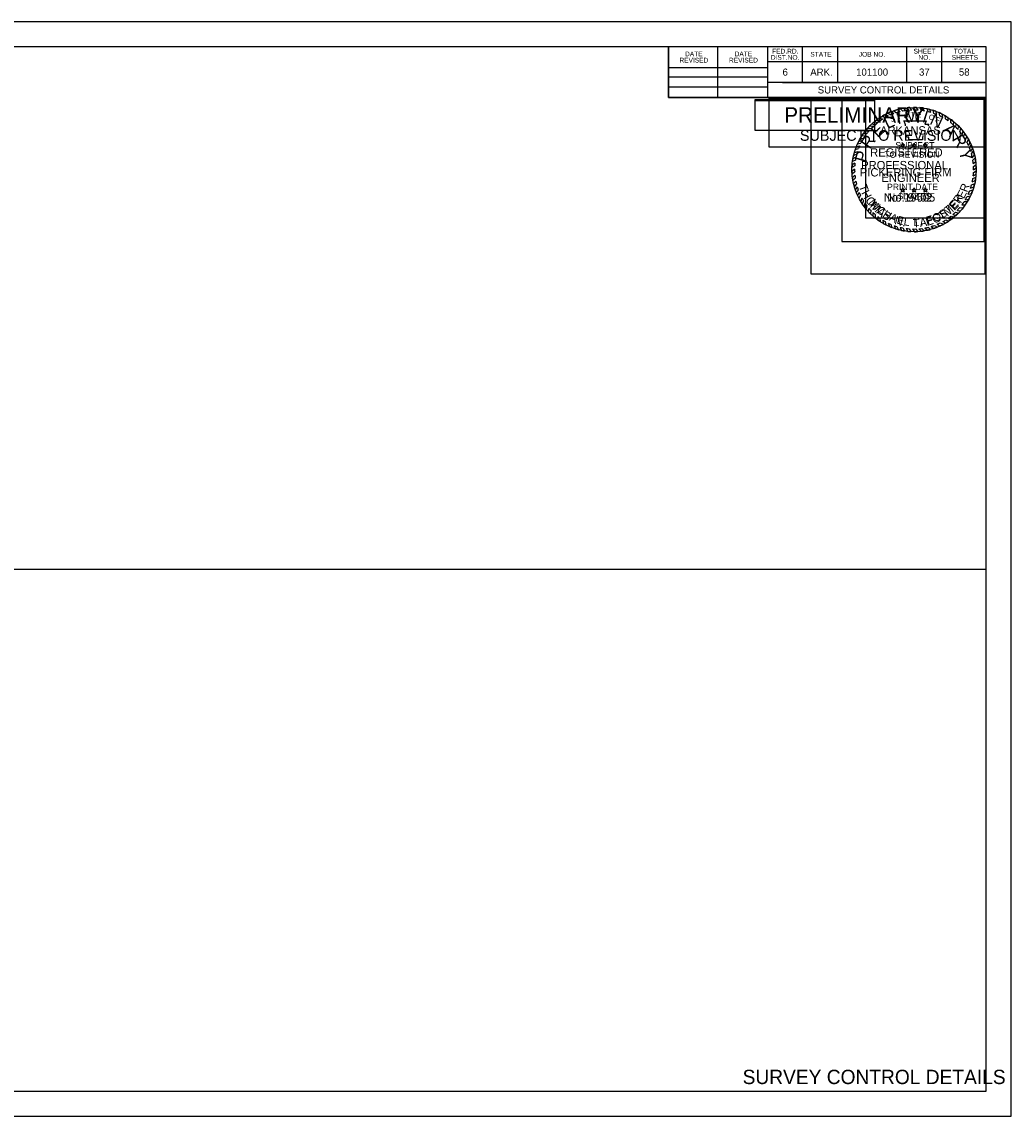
# Model space of a CAD drawing. Extents: x -0.24 to 1.42, y -0.07 to 0.92.
# Drawn here: x 0.588 to 1.417, y 0 to 0.917 of the extents above; entities that cross this region are included whole.
import ezdxf

# ---------------------------------------------------------------- set-up
doc = ezdxf.new("R2010")
doc.units = 0
for name, color, linetype in [('S_BRIDGE_ANNOT', 7, 'Continuous'), ('S_CROSS_DRAIN_ANNOT', 7, 'Continuous'), ('S_DRG_PT_SYM', 7, 'Continuous'), ('S_MSC_PT_SYM', 7, 'Continuous'), ('S_SECONDARY_CTL', 7, 'Continuous'), ('S_SIDE_DRAIN_ANNOT', 7, 'Continuous'), ('S_SURVEY_TEXT_ANNOT', 7, 'Continuous'), ('S_TELEPHONE_UTILITIES_ANNOT', 7, 'Continuous'), ('S_UNDERGROUND_CABLE', 7, 'Continuous'), ('S_UNDERGROUND_CABLE_ANNOT', 7, 'Continuous'), ('S_UTILITY_POLE', 7, 'Continuous'), ('S_UTL_PT_SYM', 7, 'Continuous')]:
    doc.layers.add(name, color=color, linetype=linetype)

msp = doc.modelspace()

# ---------------------------------------------------------------- linework, layer by layer
at = {"layer": 'S_BRIDGE_ANNOT'}
for p, q in [((1.3239, 0.84376), (1.32589, 0.84184)), ((1.32659, 0.8443), (1.32826, 0.84225)), ((1.32947, 0.84471), (1.33104, 0.84257)), ((1.33358, 0.84273), (1.33184, 0.84492)), ((1.33636, 0.84275), (1.33481, 0.84504)), ((1.33892, 0.84264), (1.33748, 0.84501)), ((1.34175, 0.84236), (1.34012, 0.84484)), ((1.34413, 0.84199), (1.34269, 0.84454)), ((1.34727, 0.84133), (1.3463, 0.8439)), ((1.34951, 0.84073), (1.34862, 0.84335)), ((1.30423, 0.83485), (1.30678, 0.8337)), ((1.30658, 0.83634), (1.30905, 0.83521)), ((1.30874, 0.8377), (1.31115, 0.83645)), ((1.31124, 0.8391), (1.31383, 0.83784)), ((1.31365, 0.84028), (1.31583, 0.83875)), ((1.31649, 0.84149), (1.31813, 0.83967)), ((1.31843, 0.8422), (1.32056, 0.84049)), ((1.32173, 0.84322), (1.32334, 0.84128)), ((1.35204, 0.83991), (1.35125, 0.84258)), ((1.35437, 0.83901), (1.35357, 0.84178)), ((1.35695, 0.83787), (1.35638, 0.84064)), ((1.35944, 0.83658), (1.35895, 0.83943)), ((1.36161, 0.83532), (1.36138, 0.83811)), ((1.36403, 0.83372), (1.36386, 0.8366)), ((1.36605, 0.83223), (1.36624, 0.83495)), ((1.2946, 0.82531), (1.29766, 0.82544)), ((1.29653, 0.82761), (1.29944, 0.8274)), ((1.29833, 0.82953), (1.30137, 0.8293)), ((1.3002, 0.83134), (1.30277, 0.83056)), ((1.30212, 0.83302), (1.30508, 0.83246)), ((1.32689, 0.8337), (1.34557, 0.8337)), ((1.32756, 0.83198), (1.32689, 0.8337)), ((1.32814, 0.83032), (1.32756, 0.83198)), ((1.32818, 0.82968), (1.32814, 0.83032)), ((1.34557, 0.8337), (1.34431, 0.83095)), ((1.34431, 0.83095), (1.34785, 0.83095)), ((1.34785, 0.83095), (1.34704, 0.82968)), ((1.36854, 0.83015), (1.36865, 0.83307)), ((1.37029, 0.82851), (1.37068, 0.8313)), ((1.37229, 0.82643), (1.37267, 0.82937)), ((1.37382, 0.82466), (1.37459, 0.82729)), ((1.37563, 0.82233), (1.37639, 0.82512)), ((1.28907, 0.81672), (1.29185, 0.81708)), ((1.29036, 0.81909), (1.29309, 0.8192)), ((1.29173, 0.82133), (1.29462, 0.82151)), ((1.29304, 0.82325), (1.29586, 0.82322)), ((1.32925, 0.82013), (1.32911, 0.82135)), ((1.33101, 0.82013), (1.32925, 0.82013)), ((1.33101, 0.81773), (1.33101, 0.82013)), ((1.34235, 0.81773), (1.33101, 0.81773)), ((1.34243, 0.81962), (1.34235, 0.81773)), ((1.34287, 0.82135), (1.34243, 0.81962)), ((1.37686, 0.82057), (1.37786, 0.82316)), ((1.37858, 0.81779), (1.3796, 0.82053)), ((1.3797, 0.81574), (1.38096, 0.81822)), ((1.28527, 0.80705), (1.28794, 0.80799)), ((1.28615, 0.80986), (1.28886, 0.81062)), ((1.28699, 0.81213), (1.28981, 0.81295)), ((1.28802, 0.81455), (1.29082, 0.81513)), ((1.32525, 0.81292), (1.32414, 0.81372)), ((1.32414, 0.81372), (1.32551, 0.81372)), ((1.32482, 0.81161), (1.32525, 0.81292)), ((1.32593, 0.81242), (1.32482, 0.81161)), ((1.32551, 0.81372), (1.32593, 0.81503)), ((1.32593, 0.81503), (1.32635, 0.81372)), ((1.32704, 0.81161), (1.32593, 0.81242)), ((1.32635, 0.81372), (1.32772, 0.81372)), ((1.32772, 0.81372), (1.32662, 0.81292)), ((1.32662, 0.81292), (1.32704, 0.81161)), ((1.33473, 0.81292), (1.33362, 0.81372)), ((1.33362, 0.81372), (1.33499, 0.81372)), ((1.33431, 0.81161), (1.33473, 0.81292)), ((1.33542, 0.81242), (1.33431, 0.81161)), ((1.33499, 0.81372), (1.33542, 0.81503)), ((1.33542, 0.81503), (1.33584, 0.81372)), ((1.33652, 0.81161), (1.33542, 0.81242)), ((1.33584, 0.81372), (1.33721, 0.81372)), ((1.33721, 0.81372), (1.3361, 0.81292)), ((1.3361, 0.81292), (1.33652, 0.81161)), ((1.34422, 0.81292), (1.34311, 0.81372)), ((1.34311, 0.81372), (1.34448, 0.81372)), ((1.34379, 0.81161), (1.34422, 0.81292)), ((1.3449, 0.81242), (1.34379, 0.81161)), ((1.34448, 0.81372), (1.3449, 0.81503)), ((1.3449, 0.81503), (1.34533, 0.81372)), ((1.34601, 0.81161), (1.3449, 0.81242)), ((1.34533, 0.81372), (1.3467, 0.81372)), ((1.3467, 0.81372), (1.34559, 0.81292)), ((1.34559, 0.81292), (1.34601, 0.81161)), ((1.38099, 0.81304), (1.38225, 0.81575)), ((1.38177, 0.81115), (1.38325, 0.81358)), ((1.38286, 0.80809), (1.38437, 0.81074)), ((1.38346, 0.80605), (1.3851, 0.80858)), ((1.28592, 0.7984), (1.28348, 0.79683)), ((1.28625, 0.80084), (1.28376, 0.79959)), ((1.28672, 0.8034), (1.28412, 0.80201)), ((1.28469, 0.80477), (1.28732, 0.80585)), ((1.38421, 0.80293), (1.38599, 0.80543)), ((1.38459, 0.80081), (1.38657, 0.80278)), ((1.38496, 0.79796), (1.38704, 0.79984)), ((1.28571, 0.79603), (1.28336, 0.79459)), ((1.28562, 0.79327), (1.28336, 0.7914)), ((1.28566, 0.791), (1.28347, 0.78918)), ((1.38493, 0.78764), (1.38735, 0.78907)), ((1.38514, 0.79563), (1.38732, 0.79726)), ((1.38515, 0.79047), (1.38749, 0.79202)), ((1.38521, 0.79273), (1.38748, 0.79453)), ((1.28584, 0.78823), (1.28377, 0.78624)), ((1.28613, 0.78583), (1.28416, 0.78375)), ((1.28657, 0.78327), (1.28468, 0.78122)), ((1.2871, 0.78093), (1.28535, 0.77861)), ((1.38354, 0.78015), (1.38617, 0.78128)), ((1.38414, 0.78268), (1.38668, 0.78377)), ((1.38465, 0.78547), (1.38712, 0.7867)), ((1.28779, 0.77843), (1.28614, 0.7761)), ((1.28857, 0.77607), (1.287, 0.77377)), ((1.2895, 0.77369), (1.28804, 0.77133)), ((1.29046, 0.77154), (1.28919, 0.76897)), ((1.32525, 0.77545), (1.32414, 0.77625)), ((1.32414, 0.77625), (1.32551, 0.77625)), ((1.32482, 0.77414), (1.32525, 0.77545)), ((1.32593, 0.77495), (1.32482, 0.77414)), ((1.32551, 0.77625), (1.32593, 0.77755)), ((1.32593, 0.77755), (1.32635, 0.77625)), ((1.32704, 0.77414), (1.32593, 0.77495)), ((1.32635, 0.77625), (1.32772, 0.77625)), ((1.32772, 0.77625), (1.32662, 0.77545)), ((1.32662, 0.77545), (1.32704, 0.77414)), ((1.33473, 0.77545), (1.33362, 0.77625)), ((1.33362, 0.77625), (1.33499, 0.77625)), ((1.33431, 0.77414), (1.33473, 0.77545)), ((1.33542, 0.77495), (1.33431, 0.77414)), ((1.33499, 0.77625), (1.33542, 0.77755)), ((1.33542, 0.77755), (1.33584, 0.77625)), ((1.33652, 0.77414), (1.33542, 0.77495)), ((1.33584, 0.77625), (1.33721, 0.77625)), ((1.33721, 0.77625), (1.3361, 0.77545)), ((1.3361, 0.77545), (1.33652, 0.77414)), ((1.34422, 0.77545), (1.34311, 0.77625)), ((1.34311, 0.77625), (1.34448, 0.77625)), ((1.34379, 0.77414), (1.34422, 0.77545)), ((1.3449, 0.77495), (1.34379, 0.77414)), ((1.34448, 0.77625), (1.3449, 0.77755)), ((1.3449, 0.77755), (1.34533, 0.77625)), ((1.34601, 0.77414), (1.3449, 0.77495)), ((1.34533, 0.77625), (1.3467, 0.77625)), ((1.3467, 0.77625), (1.34559, 0.77545)), ((1.34559, 0.77545), (1.34601, 0.77414)), ((1.37987, 0.77052), (1.38259, 0.7709)), ((1.38077, 0.7724), (1.38349, 0.77294)), ((1.38196, 0.77527), (1.38466, 0.776)), ((1.38272, 0.77739), (1.38546, 0.77851)), ((1.29177, 0.76898), (1.29071, 0.76625)), ((1.29309, 0.76673), (1.29206, 0.7641)), ((1.29422, 0.76499), (1.29361, 0.7619)), ((1.29579, 0.76281), (1.29522, 0.75984)), ((1.37377, 0.7612), (1.37635, 0.76076)), ((1.37549, 0.7634), (1.37831, 0.76342)), ((1.37739, 0.76616), (1.38005, 0.76613)), ((1.37835, 0.76773), (1.38115, 0.76804)), ((1.29749, 0.7607), (1.297, 0.75779)), ((1.29918, 0.75881), (1.29883, 0.75589)), ((1.30098, 0.75699), (1.30081, 0.75404)), ((1.3029, 0.75524), (1.30289, 0.75229)), ((1.30492, 0.7536), (1.30502, 0.75067)), ((1.30681, 0.75221), (1.30701, 0.74931)), ((1.36385, 0.75208), (1.3663, 0.75103)), ((1.36643, 0.754), (1.36904, 0.75319)), ((1.36794, 0.75525), (1.37057, 0.75453)), ((1.37021, 0.75733), (1.37267, 0.75656)), ((1.37163, 0.75878), (1.37429, 0.75831)), ((1.30919, 0.75063), (1.30953, 0.74777)), ((1.31115, 0.74948), (1.31166, 0.74662)), ((1.31384, 0.74809), (1.31471, 0.74517)), ((1.31592, 0.74714), (1.31688, 0.74429)), ((1.31867, 0.74607), (1.31984, 0.74327)), ((1.32096, 0.74531), (1.32222, 0.74258)), ((1.3238, 0.74454), (1.32498, 0.74194)), ((1.32602, 0.74406), (1.32739, 0.7415)), ((1.32881, 0.74361), (1.33015, 0.74115)), ((1.33125, 0.74334), (1.33278, 0.74095)), ((1.33396, 0.74319), (1.33565, 0.74088)), ((1.33653, 0.74318), (1.33845, 0.74097)), ((1.33942, 0.74333), (1.34124, 0.74121)), ((1.34187, 0.74359), (1.34396, 0.74159)), ((1.34436, 0.74398), (1.34653, 0.74208)), ((1.34711, 0.74456), (1.34922, 0.74274)), ((1.34968, 0.74525), (1.352, 0.74359)), ((1.35243, 0.74616), (1.3549, 0.74466)), ((1.35477, 0.74708), (1.35714, 0.74563)), ((1.35734, 0.74825), (1.36004, 0.74707)), ((1.35962, 0.74944), (1.36195, 0.74814)), ((1.36193, 0.75081), (1.36444, 0.74972))]:
    msp.add_line(p, q, dxfattribs=at)
for radius, start, end in [(0.05208, 99.75254, 102.77648), (0.05208, 93.93815, 96.55172), (0.05208, 87.72979, 90.67067), (0.05208, 81.97315, 84.82355), (0.05208, 75.31251, 77.94263), (0.05208, 123.61993, 126.59063), (0.0498, 121.97456, 125.11001), (0.05208, 117.65441, 120.80988), (0.0498, 115.68692, 119.15827), (0.05208, 111.31242, 114.70259), (0.0498, 110.30864, 113.16588), (0.05208, 105.23389, 109.03519), (0.0498, 104.03521, 107.36155), (0.0498, 98.25799, 101.03289), (0.0498, 92.11016, 95.03666), (0.0498, 85.96279, 88.9097), (0.0498, 79.92642, 82.69597), (0.0498, 73.55748, 76.23144), (0.05208, 69.60611, 72.30577), (0.0498, 67.62483, 70.50398), (0.05208, 63.13288, 66.2704), (0.0498, 61.15575, 64.37837), (0.05208, 56.90029, 60.09423), (0.0498, 54.92383, 58.27016), (0.05208, 50.3492, 53.71593), (0.05208, 141.60556, 144.44865), (0.0498, 139.30101, 142.58729), (0.05208, 135.40208, 138.30314), (0.0498, 133.13306, 136.25623), (0.05208, 129.73259, 132.53764), (0.0498, 127.52969, 130.96829), (0.0498, 48.30163, 52.03953), (0.0498, 42.22116, 45.55119), (0.05208, 44.3405, 47.39292), (0.05208, 38.12472, 41.23157), (0.05208, 152.86398, 155.51889), (0.05208, 147.00719, 149.89904), (0.0498, 151.03153, 153.57304), (0.0498, 145.01972, 148.21036), (0.0498, 36.13503, 39.53106), (0.0498, 29.90321, 33.66454), (0.05208, 31.96138, 35.42937), (0.05208, 25.93909, 29.01247), (0.05208, 164.3068, 166.89395), (0.05208, 158.40766, 161.07015), (0.0498, 162.43309, 165.00133), (0.0498, 156.34018, 159.23194), (0.0498, 23.77322, 27.22114), (0.0498, 17.68022, 21.42509), (0.05208, 19.95381, 23.31409), (0.05208, 13.84205, 17.44468), (0.05208, 170.0003, 172.68778), (0.0498, 173.73, 176.47337), (0.0498, 167.90481, 170.90393), (0.0498, 11.54445, 15.23639), (0.0498, 5.7599, 9.06056), (0.05208, 7.58519, 10.86211), (0.05208, 175.74093, 178.2066), (0.05208, 181.72508, 184.16255), (0.0498, 179.64537, 182.26333), (0.0498, 353.86319, 357.12742), (0.0498, 359.73289, 3.06392), (0.05208, 1.72155, 4.72681), (0.05208, 355.71562, 358.95694), (0.05208, 187.42037, 190.19271), (0.05208, 193.03695, 195.99732), (0.0498, 185.45389, 188.23401), (0.0498, 191.22736, 193.98583), (0.0498, 341.77699, 345.09248), (0.0498, 348.07782, 351.34355), (0.05208, 343.89247, 347.03502), (0.05208, 349.83047, 353.08845), (0.05208, 198.89671, 201.62812), (0.0498, 196.96751, 199.83526), (0.05208, 204.54793, 207.43282), (0.0498, 202.77613, 205.47915), (0.0498, 329.55488, 333.20757), (0.0498, 335.6038, 339.18578), (0.05208, 331.40371, 334.93315), (0.05208, 337.38367, 340.99332), (0.05208, 210.86355, 213.65709), (0.0498, 208.78826, 211.79343), (0.05208, 216.61154, 219.49098), (0.0498, 214.18375, 217.27474), (0.0498, 316.65308, 320.37109), (0.0498, 323.58513, 327.44069), (0.05208, 325.44052, 328.98725), (0.05208, 222.47995, 225.38008), (0.0498, 220.39088, 223.30564), (0.05208, 228.36648, 231.34802), (0.0498, 226.24938, 229.24068), (0.0498, 232.22904, 234.93361), (0.0498, 304.82299, 308.51428), (0.05208, 306.37206, 310.20799), (0.0498, 310.77436, 314.31605), (0.05208, 312.45177, 315.66328), (0.05208, 318.28455, 321.80429), (0.05208, 234.29502, 236.94517), (0.0498, 238.22227, 240.83529), (0.05208, 240.1977, 242.86128), (0.0498, 244.32043, 246.94859), (0.05208, 246.57598, 249.15579), (0.0498, 250.34912, 253.12157), (0.05208, 252.59667, 255.32518), (0.0498, 256.50505, 259.11916), (0.0498, 262.37828, 265.20115), (0.0498, 268.3215, 271.27698), (0.0498, 274.61565, 277.44863), (0.0498, 280.34588, 283.58137), (0.05208, 282.31994, 285.37019), (0.0498, 286.64233, 289.97826), (0.05208, 288.57086, 291.97334), (0.0498, 292.87452, 296.11851), (0.05208, 294.64808, 298.21662), (0.0498, 299.07679, 302.17235), (0.05208, 300.62101, 303.87026), (0.05208, 258.44328, 261.13983), (0.05208, 264.19784, 267.10092), (0.05208, 270.25484, 273.33609), (0.05208, 276.42389, 279.43574)]:
    msp.add_arc((1.33542, 0.79296), radius, start, end, dxfattribs=at)
at = {"layer": 'S_CROSS_DRAIN_ANNOT'}
for points in [[(1.20225, 0.85171), (1.30225, 0.85171), (1.30225, 0.82578), (1.20225, 0.82578)], [(1.39417, 0.85171), (1.275, 0.85171), (1.275, 0.73255), (1.39417, 0.73255)]]:
    msp.add_lwpolyline(points, close=True, dxfattribs=at)
at = {"layer": 'S_MSC_PT_SYM'}
msp.add_line((1.34483, 0.80238), (1.34483, 0.80238), dxfattribs=at)
for points in [[(1.249, 0.70571), (1.39483, 0.70571), (1.39483, 0.85238), (1.249, 0.85238)], [(1.29483, 0.75238), (1.39483, 0.75238), (1.39483, 0.85238), (1.29483, 0.85238)]]:
    msp.add_lwpolyline(points, close=True, dxfattribs=at)
at = {"layer": 'S_SIDE_DRAIN_ANNOT'}
msp.add_circle((1.33542, 0.79296), 0.05208, dxfattribs=at)
at = {"layer": 'S_TELEPHONE_UTILITIES_ANNOT'}
msp.add_lwpolyline([(1.20225, 0.85078), (1.30225, 0.85078), (1.30225, 0.82578), (1.20225, 0.82578)], close=True, dxfattribs=at)
at = {"layer": 'S_UNDERGROUND_CABLE'}
for p, q in [((1.12962, 0.85338), (1.12962, 0.89583)), ((1.17114, 0.85338), (1.17114, 0.89583)), ((1.21266, 0.89583), (1.21266, 0.85338)), ((1.24173, 0.89583), (1.24173, 0.86601)), ((1.27123, 0.89583), (1.27123, 0.86601)), ((1.32894, 0.89583), (1.32894, 0.86601)), ((1.35843, 0.89583), (1.35843, 0.86601)), ((1.39583, 0.8832), (1.21266, 0.8832)), ((1.39583, 0.88329), (1.39583, 0.88329)), ((1.12962, 0.87856), (1.21266, 0.87856)), ((1.12962, 0.87057), (1.21266, 0.87057)), ((1.12962, 0.86223), (1.21266, 0.86223)), ((1.39583, 0.86601), (1.21266, 0.86601)), ((1.22524, 0.86601), (1.39583, 0.86601)), ((1.39583, 0.85338), (1.12962, 0.85338)), ((0.02083, 0.45833), (1.39583, 0.45833))]:
    msp.add_line(p, q, dxfattribs=at)
for points in [[(0.02083, 0.02083), (1.39583, 0.02083), (1.39583, 0.89583), (0.02083, 0.89583)], [(1.12962, 0.85338), (1.39583, 0.85338), (1.39583, 0.89583), (1.12962, 0.89583)]]:
    msp.add_lwpolyline(points, close=True, dxfattribs=at)
at = {"layer": 'S_UTILITY_POLE'}
msp.add_lwpolyline([(1.21366, 0.81193), (1.39483, 0.81193), (1.39483, 0.85238), (1.21366, 0.85238)], close=True, dxfattribs=at)
msp.add_lwpolyline([(1.21366, 0.81193), (1.39483, 0.81193), (1.39483, 0.85238), (1.21366, 0.85238)], close=True, dxfattribs=at)
at = {"layer": 'S_UTL_PT_SYM'}
msp.add_lwpolyline([(0, 0), (1.41667, 0), (1.41667, 0.91667), (0, 0.91667)], close=True, dxfattribs=at)

# ---------------------------------------------------------------- texts
at = {"layer": 'S_BRIDGE_ANNOT'}
for s, rotation, p in [('S', 23.5541, (1.31642, 0.83265)), ('T', 16.311, (1.32157, 0.83473)), ('A', 9.0679, (1.32695, 0.83614)), ('T', 1.82479, (1.33246, 0.83687)), ('E', 355.20019, (1.33754, 0.83691)), ('O', 342.25065, (1.34719, 0.83537)), ('F', 335.00755, (1.35258, 0.83348))]:
    msp.add_text(s, height=0.00436, rotation=rotation, dxfattribs=at).set_placement(p)
for s, height, p in [('ARKANSAS', 0.006983, (1.30688, 0.82228)), ('REGISTERED', 0.006983, (1.29864, 0.80381)), ('PROFESSIONAL', 0.0069834, (1.29111, 0.79319)), ('ENGINEER', 0.006983, (1.30809, 0.78256))]:
    msp.add_text(s, height=height, dxfattribs=at).set_placement(p)
at = {"layer": 'S_DRG_PT_SYM'}
for s, p in [('DATE', (1.14358, 0.8878)), ('DATE', (1.1851, 0.8878)), ('FED.RD.', (1.21651, 0.89012)), ('STATE', (1.24854, 0.88752)), ('JOB NO.', (1.2891, 0.88752)), ('SHEET', (1.33496, 0.89012)), ('TOTAL', (1.36864, 0.89012)), ('REVISED', (1.13885, 0.8826)), ('REVISED', (1.18037, 0.8826)), ('DIST.NO.', (1.21541, 0.88492)), ('NO.', (1.33903, 0.88492)), ('SHEETS', (1.36685, 0.88492))]:
    msp.add_text(s, height=0.004, dxfattribs=at).set_placement(p)
at = {"layer": 'S_SECONDARY_CTL'}
for s, height, p in [('6', 0.006, (1.22524, 0.87161)), ('ARK.', 0.006, (1.24847, 0.87161)), ('101100', 0.006, (1.28686, 0.87161)), ('101100', 0.006, (1.28686, 0.87161)), ('37', 0.006, (1.33955, 0.87161)), ('58', 0.006, (1.37294, 0.87165)), ('SURVEY CONTROL DETAILS', 0.006, (1.25474, 0.8567)), ('SURVEY CONTROL DETAILS', 0.006, (1.25474, 0.8567)), ('SURVEY CONTROL DETAILS', 0.012, (1.19181, 0.02683))]:
    msp.add_text(s, height=height, dxfattribs=at).set_placement(p)
at = {"layer": 'S_SIDE_DRAIN_ANNOT'}
for s, rotation, p in [('L', 25.51305, (1.31312, 0.82664)), ('I', 12.52485, (1.32166, 0.83088)), ('M', 3.10738, (1.32779, 0.83261)), ('I', 342.31637, (1.34158, 0.83298)), ('N', 333.9382, (1.34777, 0.83145)), ('E', 42.35784, (1.30484, 0.8192)), ('A', 315.65789, (1.35913, 0.82572)), ('R', 56.22922, (1.29838, 0.80952)), ('R', 301.38306, (1.36677, 0.81838)), ('P', 73.91301, (1.29531, 0.79822)), ('Y', 283.25926, (1.37286, 0.8084))]:
    msp.add_text(s, height=0.01006, rotation=rotation, dxfattribs=at).set_placement(p)
for s, height, p in [('SUBJECT', 0.005363, (1.31977, 0.81056)), ('TO REVISION', 0.0053633, (1.31047, 0.80282)), ('PICKERING FIRM', 0.0069834, (1.29001, 0.78717)), ('PRINT DATE', 0.005363, (1.31283, 0.77573)), ('$DATE$', 0.005363, (1.3222, 0.768))]:
    msp.add_text(s, height=height, dxfattribs=at).set_placement(p)
at = {"layer": 'S_SURVEY_TEXT_ANNOT'}
for s, rotation, p in [('T', 289.64597, (1.28902, 0.77905)), ('R', 69.57001, (1.3798, 0.77349)), ('H', 296.73386, (1.29103, 0.77355)), ('Y', 53.99864, (1.37328, 0.76275)), ('E', 63.0984, (1.37702, 0.76801)), ('O', 303.77078, (1.29434, 0.76736)), ('M', 314.20329, (1.298, 0.76205)), ('M', 39.30005, (1.36334, 0.75329)), ('E', 46.80938, (1.36915, 0.7582)), ('A', 321.0594, (1.30337, 0.75666)), ('S', 327.82385, (1.30799, 0.75306)), ('N', 344.27273, (1.31858, 0.74744)), ('T', 3.00609, (1.33466, 0.74447)), ('A', 8.98261, (1.34051, 0.74478)), ('E', 17.68363, (1.34631, 0.74565)), ('G', 23.30524, (1.35218, 0.7475)), ('T', 31.46601, (1.35832, 0.75025)), ('.', 350.64643, (1.32536, 0.74559))]:
    msp.add_text(s, height=0.00698, rotation=rotation, dxfattribs=at).set_placement(p)
msp.add_text('No. 19605', height=0.006983, dxfattribs=at).set_placement((1.31006, 0.76613))
at = {"layer": 'S_UNDERGROUND_CABLE_ANNOT'}
msp.add_text('No. 9402', height=0.006983, dxfattribs=at).set_placement((1.31299, 0.76613))
for s, rotation, p in [('R', 54.5031, (1.37298, 0.76398)), ('M', 308.33902, (1.29696, 0.76515)), ('I', 314.18423, (1.30141, 0.75992)), ('C', 319.87327, (1.30339, 0.75794)), ('T', 39.41938, (1.36415, 0.7552)), ('E', 46.96131, (1.36894, 0.75939)), ('H', 327.72349, (1.30858, 0.75383)), ('A', 335.72761, (1.31406, 0.75058)), ('E', 343.5779, (1.32042, 0.74795)), ('L', 350.81148, (1.32633, 0.7464)), ('L', 1.26658, (1.33493, 0.74552)), ('F', 15.86908, (1.34679, 0.7469)), ('O', 23.71897, (1.35262, 0.74873)), ('S', 31.72336, (1.35883, 0.75169)), ('.', 6.80354, (1.34078, 0.74585))]:
    msp.add_text(s, height=0.0067, rotation=rotation, dxfattribs=at).set_placement(p)
at = {"layer": 'S_UTILITY_POLE'}
for s, height, p in [('PRELIMINARY', 0.013, (1.22664, 0.83216)), ('PRELIMINARY', 0.013, (1.22663, 0.83215)), ('SUBJECT TO REVISION', 0.009, (1.23978, 0.81704)), ('SUBJECT TO REVISION', 0.009, (1.23978, 0.81704))]:
    msp.add_text(s, height=height, dxfattribs=at).set_placement(p)

doc.saveas('drawing.dxf')
